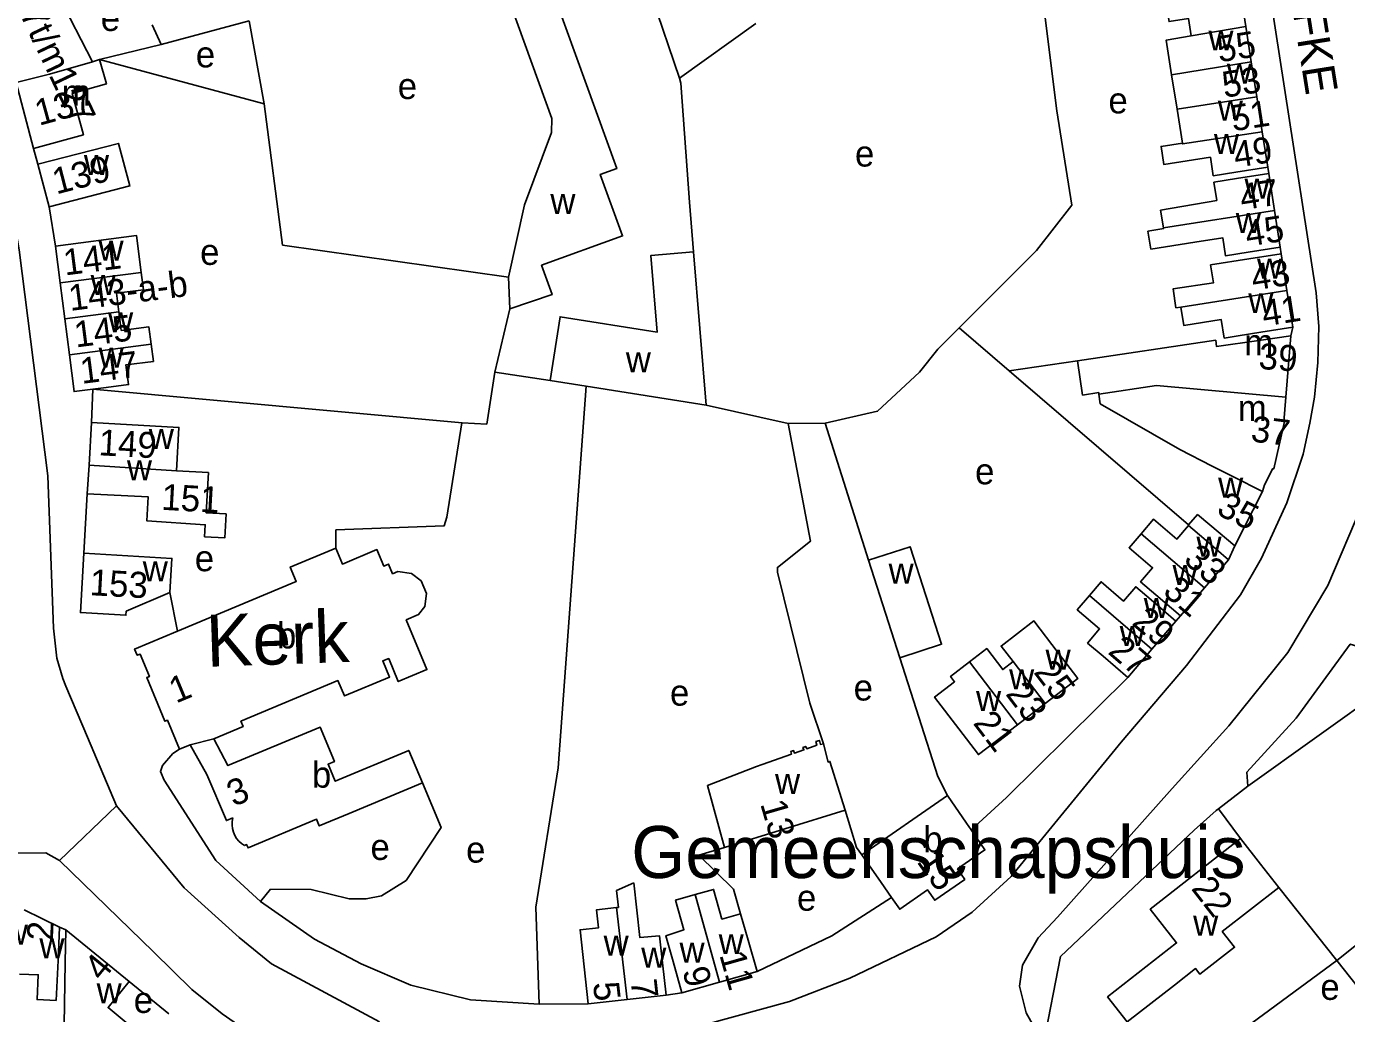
# Model space of a CAD drawing. Extents: x 162883 to 165538, y 383986 to 385172.
# Drawn here: x 164085 to 164288.3, y 384305.7 to 384457.6 of the extents above; entities that cross this region are included whole.
import ezdxf

# ---------------------------------------------------------------- set-up
doc = ezdxf.new("R2010")
doc.units = 0
for name, color, linetype in [('BLT_Basislijn', 7, 'Continuous'), ('BLT_Bebouwing', 7, 'Continuous'), ('BLT_Bebouwing_beschrifting', 7, 'Continuous'), ('BLT_Centroide', 7, 'Continuous'), ('BLT_Huisnummer', 7, 'Continuous'), ('BLT_Huisnummer_ tussenligend', 7, 'Continuous'), ('BLT_Huisnummer_reeks', 7, 'Continuous'), ('BLT_Onderverdeling_panden', 7, 'Continuous'), ('BLT_Straatnaam', 7, 'Continuous'), ('BLT_Vlakafsluiter', 7, 'Continuous')]:
    doc.layers.add(name, color=color, linetype=linetype)

msp = doc.modelspace()

# ---------------------------------------------------------------- linework, layer by layer
at = {"layer": 'BLT_Basislijn'}
for p, q in [((164170, 384495.85), (164185.54, 384449.6)), ((164119.29, 384458.45), (164121.6, 384445.67)), ((164105.77, 384454.79), (164104.39, 384457.82)), ((164185.54, 384449.6), (164197.32, 384458.02)), ((164096.29, 384452.49), (164105.77, 384454.79)), ((164086.77, 384436.4), (164086.13, 384438.81)), ((164276.14, 384435.93), (164276.28, 384434.94)), ((164089.49, 384423.79), (164088.54, 384429.83)), ((164278.06, 384423.61), (164278.18, 384422.6)), ((164159.44, 384414.11), (164157.12, 384404.4)), ((164236.31, 384404.57), (164228.61, 384411.2)), ((164279.99, 384411.3), (164279.69, 384409.97)), ((164157.12, 384404.4), (164165.63, 384403.1)), ((164095.27, 384401.78), (164095.06, 384396.64)), ((164152.09, 384396.58), (164095.27, 384401.78)), ((164166.86, 384343.53), (164171.18, 384402.23)), ((164189.65, 384399.32), (164202.28, 384396.51)), ((164202.28, 384396.51), (164208.01, 384396.55)), ((164214.68, 384375.48), (164208.01, 384396.55)), ((164132.65, 384377.33), (164132.63, 384380.15)), ((164271.06, 384377.69), (164270.07, 384375.53)), ((164261.98, 384366.09), (164262.67, 384366.88)), ((164273.08, 384340.7), (164268.52, 384337.22)), ((164271.95, 384332.65), (164268.52, 384337.22)), ((164188.52, 384330.1), (164192.51, 384331.25)), ((164286.77, 384313.86), (164277.83, 384325.11)), ((164090.11, 384319.01), (164091.09, 384318.57)), ((164106.92, 384305.67), (164100.86, 384310.64)), ((164183.49, 384308.53), (164185.93, 384308.92)), ((164163.97, 384307.14), (164171.51, 384307.21))]:
    msp.add_line(p, q, dxfattribs=at)
for points in [[(164185.25, 384302.84), (164202.51, 384307.56), (164211.78, 384311.14), (164225.1, 384317.53), (164230.64, 384321.32), (164236.62, 384326.8), (164253.57, 384347.47), (164263.64, 384359.25), (164271.91, 384370.12), (164275.19, 384375.76), (164279.07, 384384.3), (164281.58, 384391.78), (164282.61, 384396.56), (164283.32, 384400.55), (164283.86, 384405.9), (164283.97, 384411.43), (164283.58, 384416.59), (164273.81, 384479.64)], [(164073.79, 384459.86), (164077.68, 384451.03), (164078.94, 384445.85), (164082.94, 384428.86), (164083.91, 384423.22), (164088.33, 384388.44), (164089.21, 384364.99), (164089.69, 384360.4), (164090.61, 384357.27), (164091.09, 384356.07), (164094.4, 384348.23), (164098.89, 384337.66)], [(164119.29, 384458.45), (164105.77, 384454.79)], [(164241.82, 384459.3), (164243.68, 384444.62), (164245.99, 384430.1), (164240.55, 384423.1), (164228.61, 384411.2)], [(164096.29, 384452.49), (164121.6, 384445.67)], [(164185.54, 384449.6), (164185.79, 384448.83), (164187.08, 384430.53), (164187.7, 384422.89)], [(164121.6, 384445.67), (164124.47, 384423.94), (164159.24, 384419)], [(164228.61, 384411.2), (164225.31, 384407.92), (164222.49, 384404.38), (164216.07, 384398.38), (164208.01, 384396.55)], [(164157.12, 384404.4), (164155.88, 384396.39), (164152.09, 384396.58)], [(164152.09, 384396.58), (164152.05, 384396.58), (164149.77, 384382.06), (164149.32, 384380.73), (164132.63, 384380.15)], [(164207.71, 384347.21), (164205.61, 384353.46), (164200.63, 384373.61), (164200.63, 384374.34), (164205.72, 384378.38), (164202.28, 384396.51)], [(164300.18, 384395.02), (164295.59, 384393.9), (164294.19, 384393.19), (164293.14, 384391.74), (164290.67, 384383.96), (164285.39, 384371.56), (164279.22, 384361.24), (164270.12, 384349.98), (164261.4, 384340.32), (164243.74, 384320.55), (164240.78, 384317.34), (164238.38, 384313.16), (164237.93, 384309.92), (164238.95, 384305.82), (164241.62, 384301.03)], [(164093.86, 384376.53), (164094.39, 384385.68)], [(164108.3, 384364.55), (164107.1, 384370.47)], [(164305.73, 384357.37), (164288.83, 384362.54), (164280.49, 384351.18), (164272.89, 384342.84), (164273.08, 384340.7)], [(164226.81, 384339.24), (164225.36, 384342.17), (164219.49, 384360.46)], [(164230.46, 384333.97), (164235.92, 384338.96), (164254.57, 384357.43)], [(164305.73, 384357.37), (164298.1, 384352.2), (164295.09, 384355.79), (164294.3, 384355.87), (164273.08, 384340.7)], [(164108.59, 384346.39), (164107.56, 384345.7), (164105.98, 384343.86), (164105.66, 384342.97), (164106.23, 384341.61), (164114.17, 384329.26), (164121.08, 384322.97)], [(164166.86, 384343.53), (164163.47, 384322.06), (164163.97, 384307.14)], [(164121.08, 384322.97), (164122.6, 384324.85), (164128.88, 384324.77), (164134.71, 384323.34), (164137.35, 384323.38), (164139.7, 384323.81), (164143.46, 384326.2), (164148.86, 384334.33), (164146.01, 384341.21)], [(164098.89, 384337.66), (164109.3, 384325.06), (164117.75, 384317.4), (164122.73, 384313.37), (164139.36, 384304.46)], [(164213.63, 384330.11), (164212.79, 384331.28), (164211.08, 384337.02)], [(164241.62, 384301.03), (164244.24, 384314.47), (164264.79, 384333.93), (164268.2, 384336.97), (164268.52, 384337.22)], [(164083.5, 384330.4), (164088.02, 384330.42), (164090.13, 384329.25)], [(164090.13, 384329.25), (164104.56, 384315.21), (164110.51, 384309.41), (164115.15, 384305.64), (164119.37, 384302.75), (164125.75, 384298.85), (164132.5, 384295.63), (164137.45, 384293.75), (164147.6, 384290.92), (164154.24, 384289.8), (164165.92, 384289.31), (164169.7, 384289.49), (164180.44, 384290.95), (164189.84, 384293.02), (164207.02, 384297.8), (164217.62, 384300.75), (164220.05, 384300.9), (164222.45, 384300.52), (164224.73, 384299.68), (164226.1, 384298.88), (164227.04, 384297.9)], [(164188.52, 384330.1), (164193.9, 384324.87), (164194.97, 384321.07)], [(164121.08, 384322.97), (164129.37, 384317.16), (164136.56, 384313.36), (164144.22, 384310.09), (164153.4, 384307.84), (164163.97, 384307.14)], [(164218.2, 384323.58), (164209.04, 384317.66), (164197.5, 384312.19)], [(164286.77, 384313.86), (164269.82, 384301.39), (164270.2, 384298.36)]]:
    msp.add_lwpolyline(points, dxfattribs=at)
at = {"layer": 'BLT_Bebouwing'}
for p, q in [((164272.74, 384457.56), (164271.9, 384462.97)), ((164273.59, 384452.15), (164272.74, 384457.56)), ((164095.19, 384452.14), (164096.29, 384452.49)), ((164274.44, 384446.74), (164273.59, 384452.15)), ((164086.13, 384438.81), (164083.42, 384448.97)), ((164261.33, 384450.12), (164262.16, 384444.85)), ((164275.29, 384441.34), (164274.44, 384446.74)), ((164276.14, 384435.93), (164275.29, 384441.34)), ((164088.54, 384429.83), (164086.77, 384436.4)), ((164277.17, 384429.27), (164276.28, 384434.94)), ((164278.06, 384423.61), (164277.17, 384429.27)), ((164090.22, 384418.12), (164089.49, 384423.79)), ((164187.7, 384422.89), (164189.65, 384399.32)), ((164279.08, 384416.95), (164278.18, 384422.6)), ((164090.92, 384412.6), (164090.22, 384418.12)), ((164159.24, 384419), (164159.44, 384414.11)), ((164279.99, 384411.3), (164279.08, 384416.95)), ((164091.63, 384407.08), (164090.92, 384412.6)), ((164278.9, 384400.53), (164279.69, 384409.97)), ((164171.18, 384402.23), (164165.63, 384403.1)), ((164189.65, 384399.32), (164171.18, 384402.23)), ((164094.66, 384390.07), (164095.06, 384396.64)), ((164094.39, 384385.68), (164094.66, 384390.07)), ((164275.3, 384386.03), (164271.06, 384377.69)), ((164219.49, 384360.46), (164214.68, 384375.48)), ((164270.07, 384375.53), (164266.37, 384371.2)), ((164266.37, 384371.2), (164262.67, 384366.88)), ((164261.98, 384366.09), (164258.27, 384361.76)), ((164258.27, 384361.76), (164254.57, 384357.43)), ((164241.88, 384353.41), (164237.61, 384350.14)), ((164110.22, 384347.07), (164108.59, 384346.39)), ((164226.81, 384339.24), (164213.63, 384330.11)), ((164192.51, 384331.25), (164211.08, 384337.02)), ((164090.11, 384319.01), (164084.65, 384321.68)), ((164100.86, 384310.64), (164091.09, 384318.57)), ((164291.34, 384317.5), (164286.77, 384313.86)), ((164197.5, 384312.19), (164191.71, 384310.55)), ((164191.71, 384310.55), (164185.93, 384308.92)), ((164183.49, 384308.53), (164177.5, 384307.87)), ((164177.5, 384307.87), (164171.51, 384307.21))]:
    msp.add_line(p, q, dxfattribs=at)
for points in [[(164161.7, 384474.98), (164175.9, 384435.72), (164173.36, 384434.8), (164176.79, 384425.34), (164164.32, 384420.83), (164165.94, 384416.33), (164159.44, 384414.11)], [(164159.24, 384419), (164161.7, 384430.15), (164165.87, 384441.28), (164165.91, 384443.39), (164155.34, 384472.63)], [(164095.19, 384452.14), (164089.99, 384462.23), (164092.57, 384463.51), (164093.65, 384461.32), (164100.9, 384464.91)], [(164271.9, 384462.97), (164266.96, 384462.19), (164263.49, 384461.65), (164260.44, 384461.22), (164260.93, 384458.33), (164263.94, 384458.8), (164264.35, 384456.15)], [(164264.35, 384456.15), (164260.49, 384455.48), (164261.33, 384450.12)], [(164096.29, 384452.49), (164097.33, 384448.73), (164092.06, 384447.28), (164093.8, 384440.91), (164086.13, 384438.81)], [(164262.16, 384444.85), (164262.98, 384439.64)], [(164086.77, 384436.4), (164099.18, 384439.59), (164100.96, 384433.05), (164088.54, 384429.83)], [(164262.98, 384439.64), (164259.7, 384439.12), (164260.13, 384436.33), (164267.29, 384437.46), (164267.73, 384434.61), (164271.2, 384435.15), (164276.14, 384435.93)], [(164276.28, 384434.94), (164271.34, 384434.16), (164267.85, 384433.61), (164268.29, 384430.79)], [(164268.29, 384430.79), (164259.62, 384429.29), (164260.09, 384426.59)], [(164260.09, 384426.59), (164260.11, 384426.49), (164257.69, 384426.07), (164258.13, 384423.33), (164264.92, 384424.39), (164269.19, 384425.06), (164269.62, 384422.29), (164273.12, 384422.83), (164278.06, 384423.61)], [(164089.49, 384423.79), (164101.98, 384425.39), (164102.7, 384419.71)], [(164165.63, 384403.1), (164167.18, 384412.91), (164182.13, 384410.56), (164181.16, 384422.35), (164187.7, 384422.89)], [(164278.18, 384422.6), (164273.24, 384421.82), (164267.32, 384420.89), (164267.76, 384418.13), (164261.56, 384417.2), (164261.99, 384414.3), (164262.75, 384414.41)], [(164102.7, 384419.71), (164103.04, 384417.07), (164098.9, 384416.55), (164099.27, 384413.66)], [(164262.75, 384414.41), (164263.2, 384411.57), (164268.97, 384412.47), (164269.42, 384409.64), (164271.55, 384409.97), (164275.05, 384410.52), (164279.99, 384411.3)], [(164099.27, 384413.66), (164099.63, 384410.82), (164103.88, 384411.36), (164104.23, 384408.68)], [(164279.69, 384409.97), (164274.74, 384409.25), (164268.26, 384408.32), (164268.12, 384409.3), (164246.84, 384406.14)], [(164104.23, 384408.68), (164104.56, 384406.05), (164100.35, 384405.52), (164100.74, 384402.48), (164097.31, 384402.04), (164095.27, 384401.78)], [(164095.27, 384401.78), (164092.35, 384401.41), (164091.63, 384407.08)], [(164236.31, 384404.57), (164246.84, 384406.14)], [(164271.06, 384377.69), (164267.22, 384380.89), (164265.32, 384382.47), (164263.92, 384380.88), (164236.31, 384404.57)], [(164275.3, 384386.03), (164275.65, 384387.03), (164276.93, 384389.55), (164277.04, 384389.49), (164278.73, 384396.78), (164278.58, 384396.77), (164278.9, 384400.53)], [(164095.06, 384396.64), (164108.49, 384395.88), (164108.1, 384389.23)], [(164108.1, 384389.23), (164113.03, 384388.93), (164112.67, 384382.75), (164115.76, 384382.58), (164115.56, 384378.89), (164112.46, 384379.06), (164112.56, 384380.9), (164103.58, 384381.49), (164103.78, 384385.19), (164094.39, 384385.68)], [(164270.07, 384375.53), (164266.27, 384378.78), (164263.93, 384380.78), (164262.15, 384378.7), (164258.54, 384381.78), (164256.63, 384379.54)], [(164256.63, 384379.54), (164254.78, 384377.38), (164258.39, 384374.3), (164256.54, 384372.14), (164258.89, 384370.11), (164262.67, 384366.88)], [(164108.3, 384364.55), (164126.57, 384372.19), (164125.65, 384374.4), (164132.65, 384377.33)], [(164113.85, 384347.97), (164118.38, 384349.86), (164118.03, 384350.69), (164132.98, 384356.93), (164133.97, 384354.57), (164140.92, 384357.47), (164139.88, 384359.95), (164140.79, 384360.33), (164142.27, 384356.79), (164146.69, 384358.63), (164143.49, 384366.28), (164145.4, 384367.08), (164146.34, 384368.31), (164146.6, 384370.36), (164145.79, 384372.3), (164144.3, 384373.43), (164142.2, 384373.71), (164141.39, 384373.37), (164140.77, 384374.87), (164140.04, 384374.56), (164138.99, 384377.08), (164133.68, 384374.86), (164132.65, 384377.33)], [(164214.68, 384375.48), (164221.1, 384377.54), (164225.91, 384362.52), (164219.49, 384360.46)], [(164093.86, 384376.53), (164093.33, 384367.41), (164100.35, 384367), (164100.38, 384367.6), (164107.1, 384370.47)], [(164107.1, 384370.47), (164107.41, 384375.74), (164093.86, 384376.53)], [(164261.98, 384366.09), (164258.18, 384369.35), (164255.81, 384371.37), (164253.93, 384369.18), (164250.48, 384372.13), (164248.66, 384370.01)], [(164248.66, 384370.01), (164246.8, 384367.84), (164250.25, 384364.88), (164248.4, 384362.71), (164250.77, 384360.68), (164254.57, 384357.43)], [(164241.88, 384353.41), (164246.91, 384357.26), (164243.87, 384361.23), (164240.13, 384366.12), (164235.07, 384362.25), (164236.94, 384359.86)], [(164108.59, 384346.39), (164106.73, 384350.84), (164106.34, 384350.68), (164103.54, 384357.39), (164103.96, 384357.56), (164102.52, 384361.02), (164102.08, 384360.84), (164101.68, 384361.79), (164108.3, 384364.55)], [(164236.94, 384359.86), (164235.33, 384358.63), (164232.87, 384361.85), (164230.22, 384359.82)], [(164230.22, 384359.82), (164227.3, 384357.58), (164227.92, 384356.77), (164224.83, 384354.41), (164228.55, 384349.51), (164231.58, 384345.54), (164237.61, 384350.14)], [(164113.85, 384347.97), (164116.03, 384343.85), (164130.22, 384349.78), (164132.44, 384344.48), (164131.47, 384344.07), (164132.56, 384341.46), (164143.87, 384346.2), (164146.01, 384341.21)], [(164116.79, 384335.8), (164115.81, 384335.39), (164112.82, 384342.51), (164110.22, 384347.07)], [(164207.71, 384347.21), (164207.26, 384347.11), (164207.11, 384347.74), (164206.57, 384347.59), (164206.73, 384347), (164205.15, 384346.44), (164204.99, 384346.81), (164204.57, 384346.64), (164204.72, 384346.27), (164203.25, 384345.79), (164203.13, 384346.17), (164202.68, 384346.02), (164202.8, 384345.64), (164198.29, 384344.01), (164197.44, 384343.72), (164189.87, 384340.81), (164192.51, 384331.25)], [(164207.71, 384347.21), (164208.44, 384344.4), (164208.73, 384344.5), (164211.08, 384337.02)], [(164146.01, 384341.21), (164134.72, 384336.49), (164130.1, 384334.57), (164129.68, 384335.59), (164119.14, 384331.19), (164118.92, 384331.71), (164118.58, 384331.57)], [(164230.46, 384333.97), (164229.75, 384335), (164226.81, 384339.24)], [(164116.79, 384335.8), (164116.69, 384335.26), (164116.68, 384334.71), (164116.74, 384334.16), (164116.88, 384333.63), (164117.1, 384333.12), (164117.38, 384332.65), (164117.74, 384332.23), (164118.15, 384331.86), (164118.58, 384331.57)], [(164218.2, 384323.58), (164219.46, 384321.76), (164223.75, 384324.72), (164224.85, 384323.14), (164229.49, 384326.35), (164228.37, 384327.97), (164232.59, 384330.88), (164230.46, 384333.97)], [(164277.83, 384325.11), (164269.13, 384318.33), (164271.02, 384315.9), (164265.69, 384311.75), (164265.02, 384312.62), (164261.77, 384310.1), (164254.48, 384304.42), (164251.46, 384308.28), (164262.09, 384316.57), (164258.05, 384321.75), (164271.95, 384332.65)], [(164271.95, 384332.65), (164275.02, 384328.71), (164277.83, 384325.11)], [(164213.63, 384330.11), (164216.61, 384325.87), (164218.2, 384323.58)], [(164175.86, 384324.65), (164178.53, 384325.82)], [(164175.86, 384322.02), (164176.15, 384322.05), (164175.86, 384324.65)], [(164178.53, 384325.82), (164179.46, 384317.4), (164182.48, 384317.69), (164182.94, 384313.5), (164183.49, 384308.53)], [(164187.96, 384324.01), (164190.82, 384324.81), (164192.1, 384320.25), (164194.97, 384321.07)], [(164185.93, 384308.92), (164184.57, 384313.73), (164183.46, 384317.68), (164186.25, 384318.6), (164184.96, 384323.16), (164187.96, 384324.01)], [(164171.51, 384307.21), (164170.25, 384318.59), (164173.11, 384318.9), (164172.81, 384321.68), (164175.86, 384322.02)], [(164197.5, 384312.19), (164196.15, 384317), (164194.97, 384321.07)], [(164090.11, 384319.01), (164089.89, 384313.86), (164089.61, 384307.73)], [(164091.09, 384318.57), (164090.99, 384313.57), (164090.81, 384303.95)], [(164286.77, 384313.86), (164292.06, 384307.21), (164296.61, 384310.83)], [(164083.96, 384311.76), (164086.84, 384311.68), (164086.66, 384307.86), (164089.61, 384307.73)], [(164100.71, 384304.09), (164097.58, 384306.63), (164100.86, 384310.64)]]:
    msp.add_lwpolyline(points, dxfattribs=at)
at = {"layer": 'BLT_Onderverdeling_panden'}
for p, q in [((164264.35, 384456.15), (164272.74, 384457.56)), ((164261.33, 384450.12), (164273.59, 384452.15)), ((164262.16, 384444.85), (164274.44, 384446.74)), ((164277.17, 384429.27), (164260.09, 384426.59)), ((164102.7, 384419.71), (164090.22, 384418.12)), ((164279.08, 384416.95), (164262.75, 384414.41)), ((164099.27, 384413.66), (164090.92, 384412.6)), ((164104.23, 384408.68), (164091.63, 384407.08)), ((164246.84, 384406.14), (164247.63, 384400.87)), ((164247.63, 384400.87), (164250.1, 384401.24)), ((164250.1, 384401.24), (164250.13, 384401.02)), ((164094.66, 384390.07), (164108.1, 384389.23)), ((164266.37, 384371.2), (164256.63, 384379.54)), ((164258.27, 384361.76), (164248.66, 384370.01)), ((164230.22, 384359.82), (164237.61, 384350.14)), ((164236.94, 384359.86), (164241.88, 384353.41)), ((164110.22, 384347.07), (164113.85, 384347.97)), ((164191.71, 384310.55), (164187.96, 384324.01)), ((164177.5, 384307.87), (164175.86, 384322.02))]:
    msp.add_line(p, q, dxfattribs=at)
for points in [[(164083.42, 384448.97), (164088.57, 384450.26), (164095.19, 384452.14)], [(164262.98, 384439.64), (164263, 384439.51), (164275.29, 384441.34)], [(164250.13, 384401.02), (164259, 384402.34), (164278.9, 384400.53)], [(164250.13, 384401.02), (164250.35, 384399.54), (164262.6, 384392.49), (164267.58, 384389.95), (164270.84, 384388.3), (164275.3, 384386.03)]]:
    msp.add_lwpolyline(points, dxfattribs=at)
at = {"layer": 'BLT_Vlakafsluiter'}
msp.add_line((164098.89, 384337.66), (164090.13, 384329.25), dxfattribs=at)

# ---------------------------------------------------------------- texts
at = {"layer": 'BLT_Bebouwing_beschrifting'}
msp.add_text('Kerk', height=8, rotation=1.9926, dxfattribs=at).set_placement((164112.82, 384359.05))
msp.add_text('Gemeenschapshuis', height=8, dxfattribs=at).set_placement((164178.14, 384326.56))
at = {"layer": 'BLT_Centroide'}
for s, p in [('e', (164096.47, 384456.88)), ('w', (164266.99, 384453.88)), ('e', (164111.1, 384451.28)), ('w', (164269.82, 384448.78)), ('m', (164090.45, 384445.39)), ('e', (164142.19, 384446.41)), ('e', (164251.6, 384444.2)), ('w', (164268.44, 384443.09)), ('w', (164267.84, 384437.97)), ('e', (164212.58, 384436.02)), ('w', (164093.87, 384434.72)), ('w', (164272.55, 384431.09)), ('w', (164165.68, 384428.72)), ('w', (164271.21, 384425.78)), ('w', (164096.12, 384421.56)), ('e', (164111.76, 384420.89)), ('w', (164274.48, 384418.78)), ('w', (164094.9, 384416.28)), ('w', (164273.13, 384413.47)), ('w', (164097.59, 384410.5)), ('m', (164272.51, 384407)), ('w', (164096.14, 384405.09)), ('w', (164177.3, 384404.38)), ('m', (164271.52, 384396.86)), ('w', (164103.86, 384392.56)), ('w', (164100.49, 384387.76)), ('e', (164231.07, 384387.13)), ('w', (164268.49, 384385.09)), ('w', (164265.15, 384376)), ('w', (164102.93, 384372.2)), ('e', (164110.94, 384373.76)), ('w', (164217.75, 384371.87)), ('w', (164261.46, 384371.66)), ('w', (164257.04, 384366.56)), ('b', (164123.59, 384361.88)), ('w', (164253.34, 384362.25)), ('w', (164241.92, 384358.61)), ('e', (164212.37, 384353.87)), ('w', (164236.31, 384355.61)), ('e', (164184.1, 384353.08)), ('w', (164231.22, 384352.27)), ('b', (164128.98, 384340.47)), ('w', (164200.27, 384339.5)), ('b', (164223.11, 384330.5)), ('e', (164137.99, 384329.34)), ('e', (164152.71, 384328.93)), ('e', (164203.65, 384321.53)), ('w', (164264.64, 384317.69)), ('w', (164081.39, 384316.33)), ('w', (164087.02, 384314.19)), ('w', (164173.88, 384314.64)), ('w', (164185.57, 384313.54)), ('w', (164191.59, 384314.85)), ('w', (164179.67, 384312.77)), ('w', (164095.83, 384307.3)), ('e', (164284.23, 384307.81)), ('e', (164101.54, 384305.8))]:
    msp.add_text(s, height=4, dxfattribs=at).set_placement(p)
at = {"layer": 'BLT_Huisnummer'}
for s, rotation, p in [('53', 8.9152, (164269.43, 384446.59)), ('137', 15.3373, (164086.96, 384442.28)), ('49', 8.9178, (164271.19, 384435.83)), ('139', 14.5048, (164089.62, 384431.72)), ('47', 8.9178, (164272.16, 384429.29)), ('45', 8.9178, (164272.98, 384423.69)), ('141', 7.2724, (164090.96, 384419.26)), ('43', 8.9065, (164273.91, 384416.94)), ('41', 8.9065, (164275.55, 384411.41)), ('147', 7.2729, (164093.55, 384402.58)), ('39', 355.9163, (164274.63, 384404.9)), ('37', 352.9162, (164273.39, 384393.75)), ('149', 356.8704, (164096.06, 384391.61)), ('151', 356.8704, (164105.73, 384383.22)), ('35', 333.0608, (164268.05, 384382.62)), ('33', 319.4437, (164262.98, 384375.26)), ('153', 356.8704, (164094.69, 384370.08)), ('31', 319.4447, (164259.79, 384370.35)), ('29', 319.4447, (164255.04, 384365.65)), ('27', 319.4447, (164251.37, 384361.19)), ('25', 307.3133, (164239.98, 384358.2)), ('1', 22.6621, (164108.04, 384353.38)), ('21', 307.4016, (164230.65, 384350.37)), ('3', 22.6612, (164116.93, 384337.49)), ('13', 286.032, (164197.97, 384337.99)), ('15', 305.0689, (164221.99, 384329.09)), ('22', 307.9331, (164264.23, 384324.92)), ('2', 87.5433, (164089.09, 384316.86)), ('4', 50.6493, (164096.65, 384310.51)), ('11', 285.7707, (164191.68, 384314.74)), ('9', 285.7707, (164185.97, 384312.31)), ('5', 276.3035, (164172.24, 384310.41)), ('7', 276.3035, (164178.04, 384310.83))]:
    msp.add_text(s, height=4, rotation=rotation, dxfattribs=at).set_placement(p)
at = {"layer": 'BLT_Huisnummer_ tussenligend'}
for s, rotation, p in [('55', 8.9152, (164268.63, 384452.05)), ('51', 8.9178, (164270.77, 384441.43)), ('145', 7.2729, (164092.63, 384408.18)), ('23', 307.4016, (164235.65, 384354.86))]:
    msp.add_text(s, height=4, rotation=rotation, dxfattribs=at).set_placement(p)
at = {"layer": 'BLT_Huisnummer_reeks'}
for s, rotation, p in [('117t/m127', 295.4373, (164081.38, 384464.89)), ('143-a-b', 7.2729, (164091.76, 384413.8))]:
    msp.add_text(s, height=4, rotation=rotation, dxfattribs=at).set_placement(p)
at = {"layer": 'BLT_Straatnaam'}
msp.add_text("'T HOFKE", height=5, rotation=279.0311, dxfattribs=at).set_placement((164277.29, 384476.74))

doc.saveas('drawing.dxf')
